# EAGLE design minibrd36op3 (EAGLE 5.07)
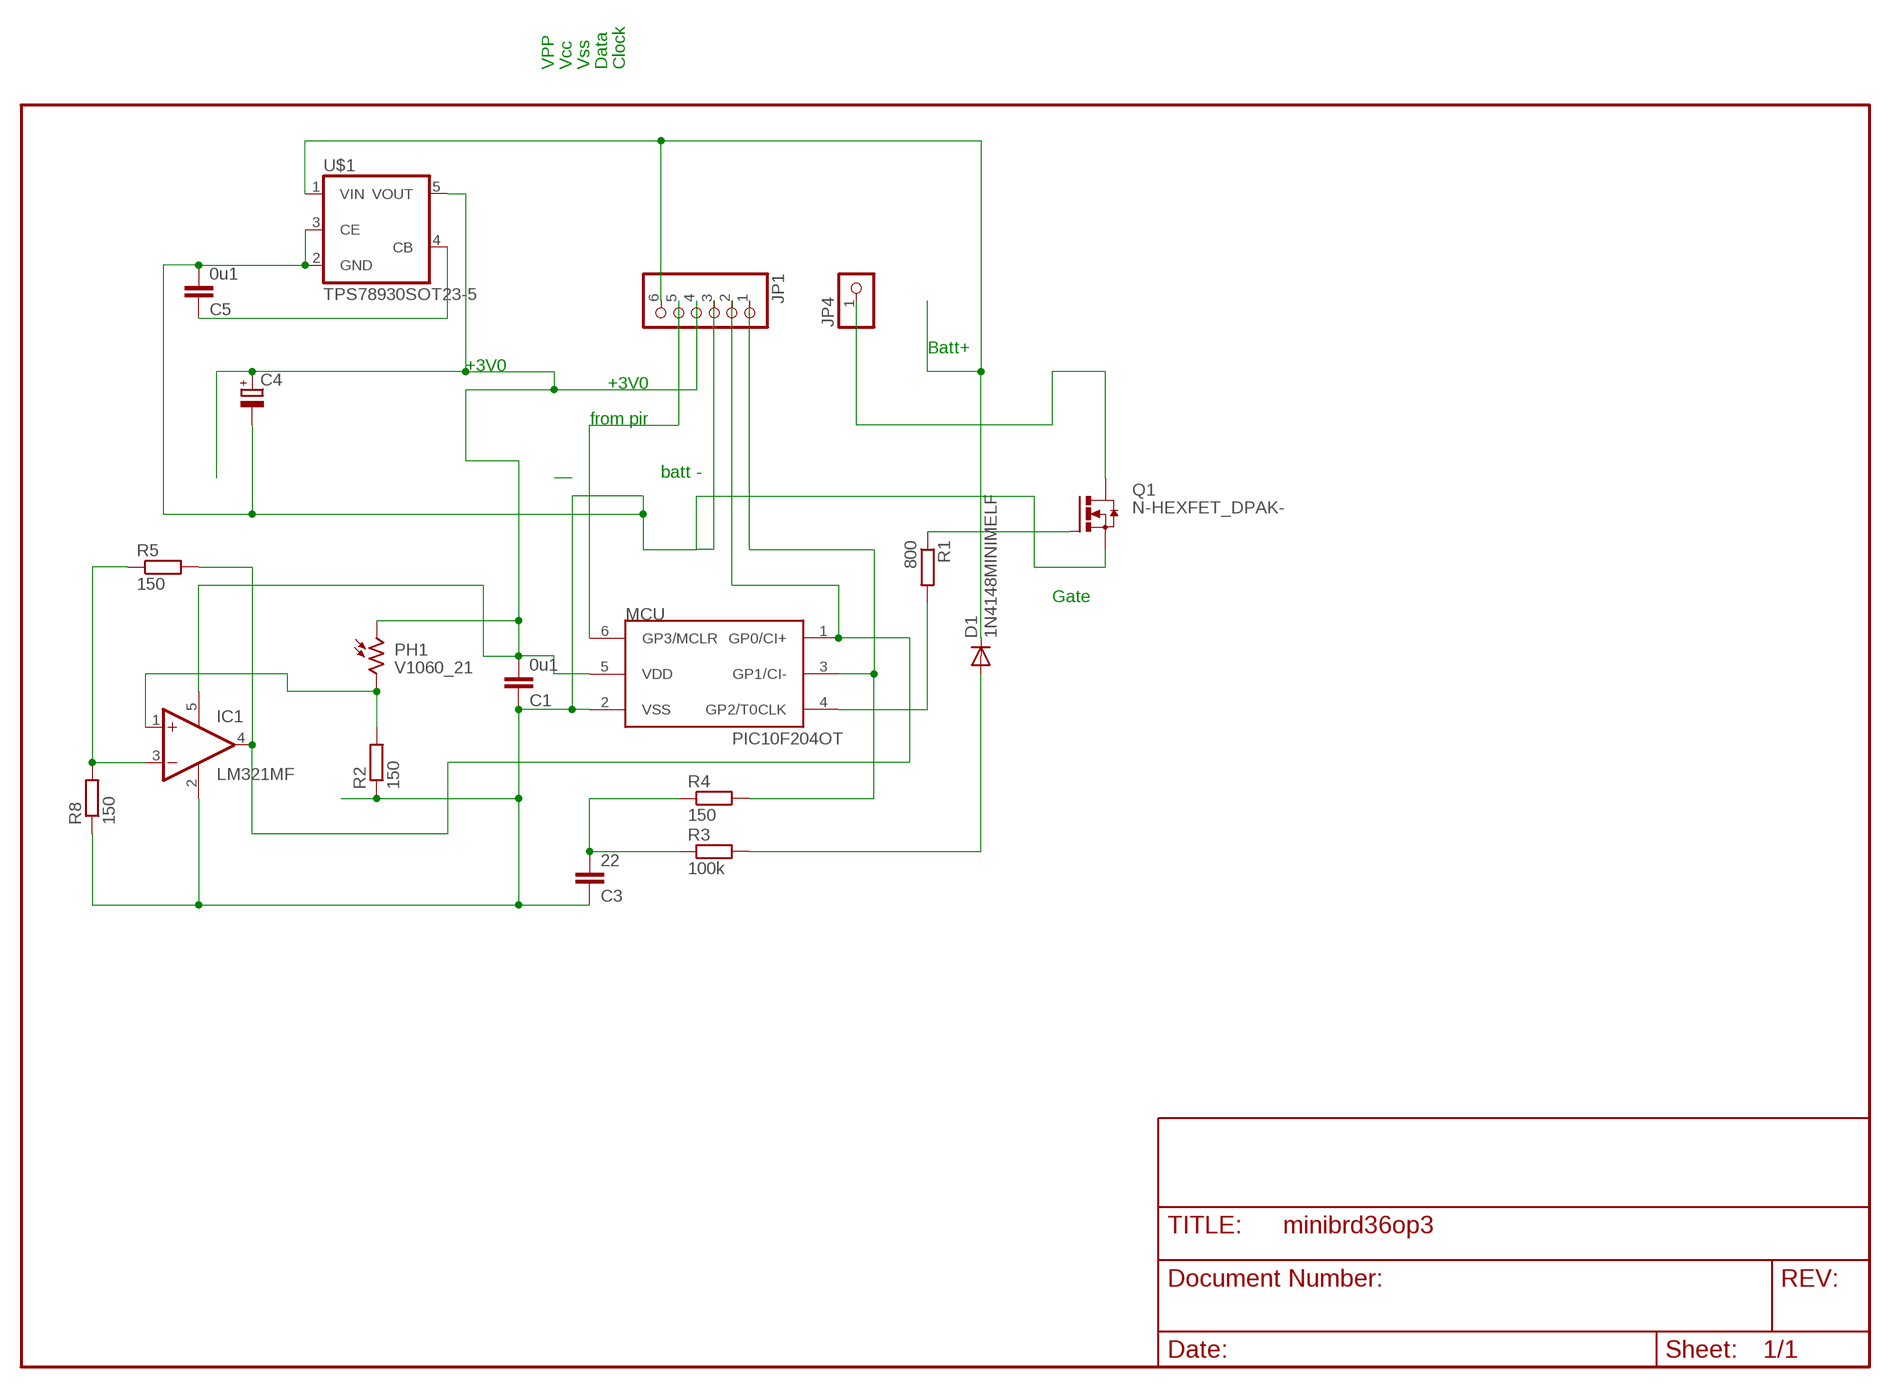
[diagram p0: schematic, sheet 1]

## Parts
C1  0u1  C-EUC1206  [C1206]
C3  22  C-EUC0805  [C0805]
C4  CPOL-EUSMCA  [SMC_A]
C5  0u1  C-EUC0805  [C0805]
D1  1N4148MINIMELF  [MINIMELF]
IC1  LM321MF  [SOT23-5]
JP1  PINHD-1X6  [1X06BOX]
JP4  PINHD-1X1  [1X01]
MCU  PIC10F204OT  [SOT23-6]
PH1  V1060_21  [TO-5_V10]
Q1  N-HEXFET_DPAK-  [TO252]
R1  800  R-EU_R0805  [R0805]
R2  150  R-EU_R0805  [R0805]
R3  100k  R-EU_R1206  [R1206]
R4  150  R-EU_R1206  [R1206]
R5  150  R-EU_R1206  [R1206]
R8  150  R-EU_R0805  [R0805]
U$1  TPS78930SOT23-5  [SOT25]

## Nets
BATT+: D1.C JP1.6 U$1.1(VIN)
HOT: JP4.1 Q1.3(D)
N$1: Q1.1(G) R1.1
N$4: IC1.4(OUT) JP1.2 MCU.1(GP0/CI+) R5.2
N$5: MCU.4(GP2/T0CLK) R1.2
N$6: IC1.1(+IN) PH1.2 R2.2
N$7: C3.2 R3.1 R4.1
N$8: JP1.1 MCU.3(GP1/CI-) R4.2
N$10: IC1.3(-IN) R5.1 R8.2
N$11: C5.1 U$1.4(CB)
PIR: JP1.5 MCU.6(GP3/MCLR)
V3: C1.2 C4.+ IC1.5(V+) JP1.4 MCU.5(VDD) PH1.1 U$1.5(VOUT)
V+: D1.A R3.2
VSS: C1.1 C3.1 C4.- C5.2 IC1.2(V-) JP1.3 MCU.2(VSS) Q1.2(S) R2.1 R8.1 U$1.2(GND) U$1.3(CE)

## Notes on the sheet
- VPP | Vcc | Vss | Data | Clock
- Batt+
- +3V0
- +3V0
- from pir
- batt -
- Gate

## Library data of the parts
C1 C3 C5 = rcl:C-EU: CAPACITOR, European symbol
C4 = rcl(2):CPOL-EU: POLARIZED CAPACITOR, European symbol
D1 = diode-1:1N4148: DIODE
IC1 = linear:LM321?*: Low Power Single Op Amp Source: http://cache.national.com/ds/LM/LM321.pdf
JP1 = pinhead:PINHD-1X6: PIN HEADER
JP4 = pinhead:PINHD-1X1: PIN HEADER
MCU = microchip-3:PIC10F2*: uPC nW 0,25/0,5k Program Flash memory Comparator
PH1 = photo-elements:?1060*: Sensor Street Light control
Q1 = transistor-power:N-HEXFET_?-*: HEXFET® Power MOSFET
R1-R5 R8 = rcl:R-EU_: RESISTOR, European symbol
U$1 = v-reg:TPS78930

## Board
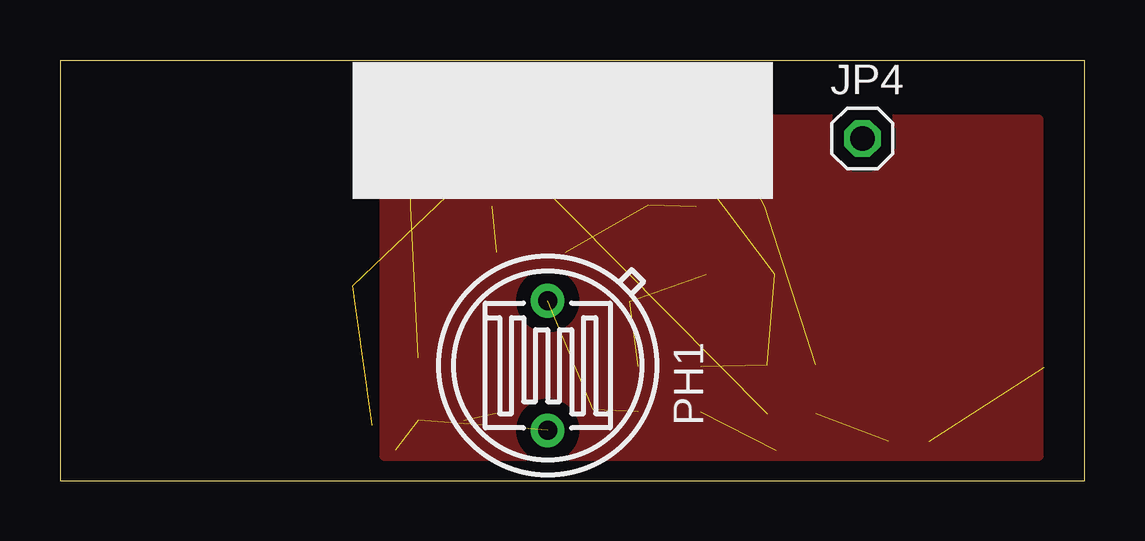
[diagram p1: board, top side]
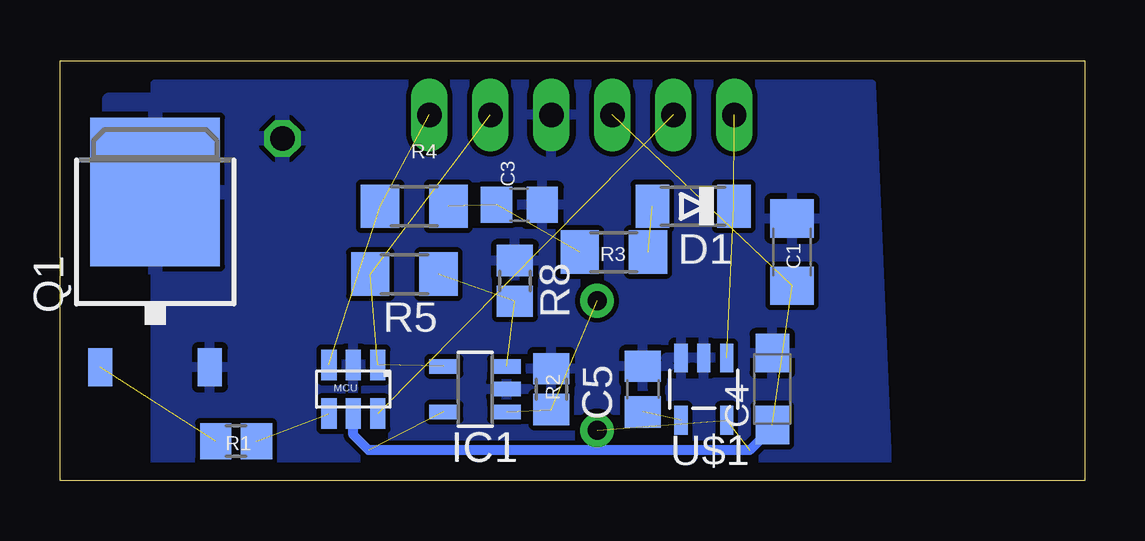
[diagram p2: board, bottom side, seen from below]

Size 42.7 x 17.5 mm. Coordinates in mm from the lower left corner, seen from the top.
Outline: 0,0 42.7,0 42.7,17.5 0,17.5 0,0
Copper layers (1*16): Top 0.035mm / dielectric 1.5mm / Bottom 0.035mm
Design rules "default *": minimum track width 10mil, minimum drill 24mil, track to track 8mil, track to pad 8mil, pad to pad 8mil, via to via 8mil, smd to smd 8mil, copper to edge 30mil, drill to drill 8mil, minimum pad ring 10mil, minimum via ring 8mil, stop-mask expansion 4mil, vias tented up to drill 0mil, thermal gap 10mil

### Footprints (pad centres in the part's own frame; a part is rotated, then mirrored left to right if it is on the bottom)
C1206 = smd 1.6 x 1.8: 1 -1.4,0; 2 1.4,0
C0805 = smd 1.3 x 1.5: 1 -0.95,0; 2 0.95,0
SMC_A = smd 1.6 x 1.4: + -1.5,0; - 1.5,0
MINIMELF = smd 1.4 x 1.8: A 1.7,0; C -1.7,0
SOT23-5 = smd 0.6 x 1.2: 1 -0.95,-1.306; 2 0,-1.306; 3 0.95,-1.306; 4 0.95,1.306; 5 -0.95,1.306
1X06BOX = drill 1.016 long: 1 -6.35,0; 2 -3.81,0; 3 -1.27,0; 4 1.27,0; 5 3.81,0; 6 6.35,0
1X01 = drill 1.016 octagon: 1 0,0
SOT23-6 = smd 0.635 x 1.27: 1 -1.016,-1.016; 2 0,-1.016; 3 1.016,-1.016; 4 1.016,1.016; 5 0,1.016; 6 -1.016,1.016
TO-5_V10 = drill 0.8 pad 1.4 round: 1 -2.7,0; 2 2.7,0
TO252 = smd 1 x 1.6: 1 -2.28,-3.53; 2 2.28,-3.53 | smd 5.4 x 6.2: 3 0,3.77
R0805 = smd 1.3 x 1.5: 1 -0.85,0; 2 0.85,0
R1206 = smd 1.6 x 1.803: 1 -1.422,0; 2 1.422,0
SOT25 = smd 0.55 x 1.2: 1 -0.95,-1.3; 2 0,-1.3; 3 0.95,-1.3; 4 0.95,1.3; 5 -0.95,1.3

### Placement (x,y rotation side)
C1  12.2,9.52 270 bottom
C3  23.56,11.49 180 bottom
C4  13.02,3.81 90 bottom
C5  18.41,3.81 90 bottom
D1  16.32,11.43 180 bottom
IC1  25.4,3.81 90 bottom
JP1  20.95,15.24 180 top
JP4  33.43,14.26 0 top
MCU  30.48,3.81 180 bottom
PH1  20.32,4.79 90 top
Q1  38.73,8.26 0 bottom
R1  35.36,1.64 0 bottom
R2  22.23,3.81 270 bottom
R3  19.62,9.53 0 bottom
R4  27.94,11.43 180 bottom
R5  28.35,8.6 180 bottom
R8  23.75,8.32 270 bottom
U$1  15.88,3.81 180 bottom

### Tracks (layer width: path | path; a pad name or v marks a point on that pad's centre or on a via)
BATT+  (2 unrouted)
HOT
  pour Bottom (isolate 0.406): 32.38,15.88 32.38,12.7 34.92,12.7 34.92,8.89 40.64,8.89 40.64,15.88
N$1  (1 unrouted)
N$4  (3 unrouted)
N$5  (1 unrouted)
N$6  (2 unrouted)
N$7  (2 unrouted)
N$8  (2 unrouted)
N$10  (2 unrouted)
N$11  (1 unrouted)
PIR  (1 unrouted)
V3  (5 unrouted)
  Bottom 0.406: C4.+ 13.02,2.22 13.97,1.27 29.84,1.27 30.48,1.91 MCU.5
V+  (1 unrouted)
VSS
  pour Top (isolate 0.61): 13.78,15.05 40.77,15.05 40.77,1.02 13.53,1.02 13.53,14.35
  pour Bottom: 8.89,16.51 38.73,16.51 38.73,0 8.26,0 8.26,1.27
